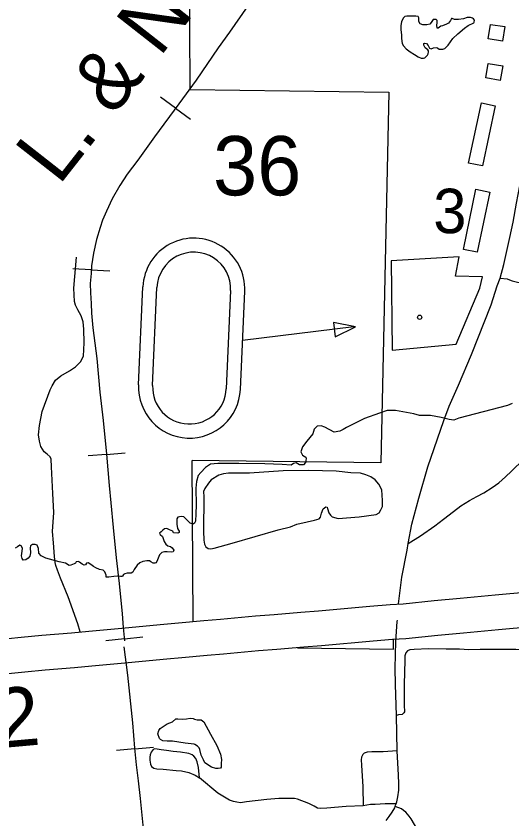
# Model space of a CAD drawing. Extents: x 61396 to 64680, y 55472 to 57605.
# Drawn here: x 62743.1 to 62853.4, y 56330.1 to 56508.8 of the extents above; entities that cross this region are included whole.
import ezdxf

# ---------------------------------------------------------------- set-up
doc = ezdxf.new("R2010")
doc.units = 0
for name, color, linetype in [('15', 7, 'Continuous'), ('33', 7, 'Continuous'), ('34', 7, 'Continuous'), ('35', 7, 'Continuous'), ('40', 7, 'Continuous'), ('48', 7, 'Continuous'), ('5', 7, 'Continuous'), ('56', 7, 'Continuous'), ('57', 7, 'Continuous'), ('6', 7, 'Continuous'), ('7', 7, 'Continuous')]:
    doc.layers.add(name, color=color, linetype=linetype)

msp = doc.modelspace()

# ---------------------------------------------------------------- linework, layer by layer
at = {"layer": '15'}
for points in [[(62738.41, 56369.93), (62744.28, 56370.54), (62748.87, 56370.99), (62755.43, 56371.52), (62759.28, 56371.87), (62766.65, 56372.54), (62768.95, 56372.72), (62775.96, 56373.42), (62779.27, 56373.69), (62784.86, 56374.24), (62788.56, 56374.57), (62796.35, 56375.24), (62800.5, 56375.57), (62806.45, 56376.07), (62810.4, 56376.39), (62821.81, 56377.41), (62826.31, 56377.8), (62829.16, 56377.92), (62836.11, 56378.7), (62841.9, 56379.23), (62849.65, 56379.94), (62857.08, 56380.61)], [(62857.78, 56372.83), (62850.36, 56372.16), (62842.61, 56371.45), (62836.9, 56370.93), (62829.76, 56370.12), (62826.8, 56370), (62822.49, 56369.63), (62811.07, 56368.6), (62807.09, 56368.28), (62801.13, 56367.78), (62797, 56367.46), (62789.24, 56366.78), (62785.59, 56366.46), (62779.97, 56365.91), (62776.66, 56365.64), (62769.63, 56364.94), (62767.3, 56364.76), (62759.99, 56364.09), (62756.09, 56363.73), (62749.56, 56363.21), (62745.06, 56362.77), (62739.07, 56362.15)]]:
    msp.add_lwpolyline(points, dxfattribs=at)
at = {"layer": '33'}
for points in [[(62850.75, 56450.39), (62851.59, 56453.46), (62852.21, 56456.17), (62852.92, 56459.47), (62853.63, 56462.9), (62854.39, 56467.13), (62855.91, 56474.83), (62857.24, 56482.13), (62859.07, 56492.04)], [(62830.28, 56391.36), (62831.1, 56395.71), (62832.7, 56401.45), (62834.69, 56408.43), (62838.22, 56418.71), (62839.46, 56421.96), (62841.47, 56426.58), (62844.4, 56433.45), (62848.8, 56444.5), (62850.11, 56448.74), (62850.75, 56450.39)], [(62828.14, 56377.95), (62828.92, 56383.9), (62830.05, 56389.91), (62830.28, 56391.36)], [(62825.39, 56329.74), (62826.08, 56330.63), (62826.78, 56331.58), (62827.34, 56332.58), (62827.44, 56332.88), (62827.52, 56333.12), (62827.62, 56333.41), (62827.78, 56333.88), (62828.01, 56334.99), (62828.21, 56336.47), (62828.25, 56337.94), (62828.17, 56339.83), (62827.88, 56345.25), (62827.69, 56353.12), (62827.52, 56359.99), (62827.44, 56363.6), (62827.57, 56369.6), (62827.88, 56374.02), (62827.9, 56374.3)], [(62862.33, 56367.78), (62857.94, 56367.71), (62854.27, 56367.82), (62851.05, 56367.78), (62846.35, 56367.78), (62843.81, 56367.71), (62841.69, 56367.85), (62838.74, 56367.85), (62834.86, 56367.92), (62831.64, 56367.82)], [(62831.64, 56367.82), (62830.78, 56367.71), (62830.71, 56367.69), (62830.13, 56367.47), (62829.79, 56367.03), (62829.58, 56366.34), (62829.58, 56365.35), (62829.41, 56360.04), (62829.41, 56355.15), (62829.51, 56354.17), (62829.48, 56353.9), (62829.35, 56353.69), (62829.15, 56353.47), (62828.95, 56353.35), (62828.17, 56353.21), (62827.69, 56353.12)], [(62844.89, 56306.79), (62844.25, 56308.66), (62840.74, 56313.99), (62834.09, 56324.8), (62832.69, 56327.19), (62830.99, 56330.09), (62830.52, 56330.69), (62829.79, 56331.6), (62829.27, 56331.98), (62828.82, 56332.33), (62827.44, 56332.88)]]:
    msp.add_lwpolyline(points, dxfattribs=at)
at = {"layer": '34'}
for points in [[(62757.35, 56371.69), (62756.88, 56373.47), (62754.67, 56379.5), (62753.01, 56383.69), (62752.34, 56385.41), (62751.93, 56386.5), (62751.79, 56387.11), (62751.63, 56388.48), (62751.45, 56391.52), (62751.22, 56394.07), (62751.5, 56398.3), (62751.31, 56402.48), (62751, 56408.44), (62750.95, 56410.13), (62750.68, 56410.67), (62750.04, 56411.26), (62749.4, 56411.76), (62748.99, 56412.4), (62748.63, 56412.99), (62748.31, 56414.17), (62748.13, 56415.58), (62748.36, 56417.63), (62748.95, 56420.78), (62750.7, 56425.57), (62751.13, 56426.48), (62751.91, 56427.7), (62753.08, 56428.7), (62755, 56429.78), (62756.33, 56430.7), (62757.46, 56431.82), (62758.09, 56433.08), (62758.25, 56436), (62758.2, 56439.1), (62758.03, 56440.72), (62757.59, 56442.01), (62756.82, 56443.39), (62756.36, 56444.4), (62756.14, 56445.2), (62755.95, 56448.22), (62756.55, 56455.09)], [(62850.75, 56450.39), (62852.3, 56450.28), (62852.84, 56450.08), (62853.46, 56449.8), (62854.61, 56449.5), (62856.32, 56449.38), (62858.37, 56449.32), (62860.28, 56449.19), (62861.23, 56449.22), (62861.77, 56449.34), (62862.4, 56449.46), (62863.1, 56449.58), (62864.1, 56449.7)], [(62830.28, 56391.36), (62833.02, 56393.05), (62836.2, 56395.27), (62838.18, 56396.79), (62841.32, 56399.23), (62842.02, 56399.78), (62843.97, 56400.92), (62845.56, 56401.81), (62847.13, 56402.65), (62849.01, 56403.81), (62850.48, 56404.89), (62851.93, 56406.2), (62853.3, 56407.5), (62855.98, 56410.05), (62857.84, 56411.74), (62861.24, 56414.64), (62863.38, 56416.55)], [(62783.92, 56339.24), (62783.7, 56341.52), (62783.38, 56342.81), (62783.07, 56343.51), (62782.65, 56344.06), (62782.27, 56344.34), (62781.5, 56344.66), (62779.65, 56344.93), (62778.05, 56345.11), (62776.55, 56345.28), (62775.4, 56345.49), (62774.5, 56345.63), (62773.99, 56345.64), (62773.63, 56345.56), (62773.14, 56344.97), (62772.9, 56344.34), (62772.83, 56343.82), (62772.86, 56343.12), (62773, 56342.25), (62773.25, 56341.73), (62773.73, 56341.38), (62774.43, 56341.21), (62775.86, 56341.17), (62778.71, 56340.86), (62779.93, 56340.76), (62781.54, 56340.44), (62782.96, 56339.81), (62783.92, 56339.24)], [(62827.88, 56345.25), (62824.77, 56345.04), (62823.84, 56345.03), (62822.22, 56345), (62821.18, 56344.97), (62820.55, 56344.73), (62820.2, 56344.45), (62819.92, 56343.82), (62819.89, 56343.23), (62819.92, 56342.01), (62820.2, 56337.24), (62820.32, 56332.97)], [(62820.32, 56332.97), (62816.51, 56332.81), (62812.23, 56332.47), (62810.73, 56332.4), (62810.14, 56332.47), (62809.4, 56332.92), (62808.22, 56333.48), (62805.71, 56334.45), (62805.01, 56334.66), (62804.42, 56334.63), (62803.8, 56334.63), (62801.57, 56334.59), (62798.85, 56334.38), (62794.39, 56333.89), (62793.03, 56333.69), (62792.2, 56333.79), (62791.43, 56333.93), (62790.59, 56334.24), (62787.98, 56335.81), (62783.92, 56339.24)], [(62827.62, 56333.41), (62825.22, 56333.41), (62822.96, 56333.31), (62821.91, 56333.27), (62820.32, 56332.97)]]:
    msp.add_lwpolyline(points, dxfattribs=at)
at = {"layer": '35'}
for points in [[(62829.28, 56502.12), (62829.86, 56501.45), (62830.76, 56500.77), (62831.75, 56500.19), (62832.56, 56499.7), (62833.19, 56499.38), (62833.68, 56499.38), (62834, 56499.47), (62834.58, 56500.05), (62834.76, 56500.37), (62834.85, 56500.77), (62834.85, 56501.04), (62834.67, 56501.27), (62834.4, 56501.45), (62834.09, 56501.67), (62833.77, 56502.26), (62833.82, 56502.62), (62834, 56502.71), (62834.36, 56502.66), (62834.76, 56502.17), (62835.08, 56501.58), (62835.39, 56501.49), (62835.93, 56501.67), (62836.65, 56501.76), (62836.88, 56501.63), (62837.19, 56501.4), (62837.46, 56501.4), (62838.04, 56501.4), (62838.49, 56501.54), (62839.21, 56502.3), (62840.25, 56503.78), (62841.32, 56504.82), (62842.85, 56506.03), (62843.66, 56506.62), (62844.88, 56507.24), (62845.01, 56507.42), (62845.06, 56507.83), (62844.83, 56508.1), (62844.61, 56508.28), (62844.16, 56508.46), (62843.39, 56508.41), (62842.63, 56508.1), (62841.5, 56507.96), (62840.61, 56508.01), (62840.11, 56508.23), (62839.93, 56508.23), (62839.71, 56507.78), (62839.3, 56507.15), (62838.85, 56506.93), (62837.95, 56506.57), (62837.55, 56506.48), (62836.97, 56506.08), (62836.74, 56506.08), (62836.7, 56506.71), (62836.74, 56507.24), (62836.74, 56507.74), (62836.52, 56508.01), (62835.89, 56508.01), (62835.71, 56507.78), (62835.44, 56507.29), (62835.12, 56506.93), (62834.45, 56506.79), (62833.59, 56506.79), (62833.01, 56507.02), (62832.65, 56507.51), (62832.65, 56507.87), (62832.65, 56508.37), (62832.52, 56508.68), (62831.98, 56508.73), (62830.9, 56508.73), (62830, 56508.73), (62829.55, 56508.68), (62829.19, 56508.32), (62828.79, 56507.47), (62828.7, 56506.66), (62828.7, 56505.67), (62828.83, 56504.59), (62828.83, 56503.87), (62828.87, 56503.19), (62828.97, 56502.66), (62829.28, 56502.12)], [(62853.42, 56422.5), (62852.41, 56422.09), (62841.54, 56419.25), (62840.48, 56418.82), (62839.43, 56418.96), (62837.61, 56419.43), (62835.26, 56419.88), (62832.86, 56419.85), (62831.54, 56420.25), (62827.5, 56420.99), (62825.67, 56421), (62823.93, 56420.39), (62820.62, 56419.18), (62816.57, 56417.17), (62815.88, 56416.73), (62815.08, 56416.37), (62813.86, 56416.15), (62811.75, 56417.24)], [(62811.75, 56417.24), (62810.97, 56417.56), (62810.05, 56417.51), (62809.42, 56416.79), (62809.09, 56415.78), (62807.75, 56414.16), (62806.83, 56412.88), (62806.41, 56411.78), (62806.8, 56411.06), (62807.54, 56410.59), (62807.66, 56410.26), (62807.48, 56409.39), (62807, 56408.88), (62806.14, 56408.88), (62805.42, 56409.3), (62804.79, 56409.18), (62804.27, 56408.84), (62802.3, 56408.95), (62798.43, 56409.07), (62792.68, 56409.15), (62788.01, 56409.15), (62786.32, 56409.01), (62785.26, 56408.32), (62784.23, 56407.21), (62783.6, 56406.49), (62783.23, 56405.2)], [(62783.23, 56405.2), (62783.11, 56403.72), (62783.18, 56399.99), (62783.12, 56397.98), (62782.98, 56396.33), (62782.78, 56395.87), (62782.47, 56395.69), (62781.82, 56395.89), (62781.29, 56396.42), (62780.44, 56397.34), (62779.86, 56397.38), (62779.08, 56397.2)], [(62779.08, 56397.2), (62778.88, 56396.87), (62778.86, 56395.64), (62779.02, 56394.71), (62779.26, 56394.37), (62779.41, 56394.11), (62779.35, 56393.83), (62779.08, 56393.66), (62778.15, 56393.77), (62777.97, 56394.15), (62777.22, 56394.41), (62776.61, 56394.69), (62776.1, 56394.67), (62775.72, 56394.34), (62775.38, 56393.96), (62775.01, 56393.67), (62775.16, 56393.41), (62775.69, 56392.91), (62776.07, 56391.85), (62776.44, 56391.22), (62776.89, 56390.87), (62777.49, 56390.67), (62777.81, 56390.4), (62778.18, 56389.9), (62778.16, 56389.68), (62778.03, 56389.49), (62777.68, 56389.48), (62777.68, 56389.48)], [(62760.31, 56386.27), (62759.76, 56386.73), (62759.16, 56387.06), (62758.75, 56386.96), (62758.52, 56386.64), (62758.27, 56386.55), (62757.83, 56386.8), (62757.2, 56387.25), (62756.94, 56387.35), (62756.5, 56387.33), (62756.36, 56386.99), (62756, 56386.83), (62755.28, 56386.53), (62754.89, 56386.5), (62754.09, 56387.01), (62752.67, 56387.26), (62749.71, 56388.13), (62748.7, 56388.66), (62748.19, 56389.21), (62748.08, 56390.27), (62747.78, 56391), (62747.34, 56391.14), (62746.75, 56391.14), (62746.36, 56390.82), (62746.22, 56390.43), (62746.29, 56389.33)], [(62746.29, 56389.33), (62746.16, 56388.57), (62745.82, 56388.13), (62745.28, 56387.74), (62744.73, 56387.69), (62744.47, 56388.02), (62744.31, 56388.62), (62744.5, 56389.69), (62744.52, 56390.31), (62744.26, 56390.89), (62743.92, 56391.03), (62743.43, 56390.66), (62742.92, 56390.33)], [(62777.68, 56389.48), (62776.71, 56389.51), (62776.12, 56389.54), (62775.56, 56389.35), (62775.03, 56388.85), (62774.7, 56388.14), (62774.42, 56387.38), (62774.22, 56387.1), (62773.97, 56386.99), (62773.59, 56387), (62773.11, 56387.3), (62772.78, 56387.51), (62772.16, 56387.55), (62771.33, 56387.37), (62770.64, 56387.05), (62770.07, 56386.55), (62769.38, 56385.59), (62769.06, 56385.03), (62768.7, 56384.79), (62767.82, 56384.79), (62767.27, 56384.65), (62767.02, 56384.47), (62766.8, 56384.11), (62766.62, 56384.02), (62766.36, 56384), (62765.67, 56384.13), (62764.85, 56384.04), (62763.78, 56383.87), (62763.18, 56383.87), (62763.14, 56384.32), (62762.84, 56385.06), (62762.49, 56385.47), (62761.64, 56385.56), (62760.84, 56385.98), (62760.31, 56386.27)], [(62782.72, 56346.75), (62780.71, 56346.96), (62777.88, 56347.37), (62776.74, 56347.37), (62775.76, 56347.47), (62775.25, 56347.73), (62775.04, 56347.99), (62774.63, 56349.02), (62774.84, 56349.79), (62775.15, 56350.21), (62776.74, 56351.24), (62777.88, 56351.7), (62778.65, 56352.32), (62779.12, 56352.32), (62780.2, 56352.27), (62781.02, 56352.32), (62781.8, 56352.47), (62782.47, 56352.42), (62782.83, 56352.27), (62783.39, 56352.11), (62783.96, 56352.11), (62784.27, 56352.11), (62784.84, 56351.65), (62786.33, 56348.97), (62787.73, 56346.39), (62788.55, 56344.48), (62788.81, 56343.3), (62788.76, 56342.42), (62788.76, 56341.6), (62788.6, 56341.39), (62788.09, 56341.29), (62787.52, 56341.29), (62786.54, 56341.6), (62785.1, 56342.58), (62784.79, 56343.25), (62784.27, 56344.28), (62783.96, 56345.52), (62783.81, 56345.88), (62783.45, 56346.29), (62782.88, 56346.65), (62782.72, 56346.75)]]:
    msp.add_lwpolyline(points, dxfattribs=at)
msp.add_lwpolyline([(62788.2, 56406.6), (62786.51, 56405.53), (62785.88, 56404.77), (62785.08, 56403.65), (62784.81, 56402.94), (62784.85, 56401.74), (62784.81, 56394.11), (62784.85, 56392.14), (62785.03, 56391.21), (62785.34, 56390.63), (62785.84, 56390.27), (62786.46, 56390.18), (62787.17, 56390.36), (62791.15, 56391.43), (62801.37, 56394.42), (62804.14, 56395.09), (62805.52, 56395.67), (62807.88, 56396.16), (62809.49, 56396.56), (62810.52, 56396.83), (62810.83, 56397.27), (62811.01, 56398.12), (62811.41, 56399.06), (62812.03, 56399.5), (62812.26, 56399.46), (62812.39, 56399.19), (62812.7, 56398.21), (62813.02, 56397.68), (62813.37, 56397.32), (62814.76, 56396.92), (62819.44, 56397.32), (62823.19, 56397.81), (62823.86, 56398.21), (62824.26, 56398.84), (62824.62, 56399.59), (62824.62, 56400.93), (62824.44, 56403.34), (62823.82, 56404.55), (62822.97, 56405.53), (62822.03, 56406.2), (62820.92, 56406.64), (62819.67, 56407.05), (62817.57, 56407.13), (62814.31, 56407.49), (62808.24, 56407.63), (62802.48, 56407.54), (62795.03, 56407.05), (62790.34, 56407), (62789.27, 56406.87)], close=True, dxfattribs=at)
at = {"layer": '40'}
for p, q in [((62778.59, 56488.26), (62775.27, 56490.71)), ((62778.59, 56488.26), (62781.92, 56485.82)), ((62759.84, 56452.26), (62755.72, 56452.48)), ((62759.84, 56452.26), (62763.96, 56452.03)), ((62763.24, 56411.21), (62759.13, 56410.85)), ((62763.24, 56411.21), (62767.35, 56411.57)), ((62767.2, 56370.15), (62763.1, 56369.68)), ((62767.2, 56370.15), (62771.3, 56370.61)), ((62769.56, 56345.69), (62765.45, 56345.33)), ((62769.56, 56345.69), (62773.67, 56346.05))]:
    msp.add_line(p, q, dxfattribs=at)
for points in [[(62794.66, 56511.05), (62790.55, 56505.18), (62788.08, 56501.71), (62783.15, 56494.46), (62779.28, 56489.2), (62773.89, 56481.86), (62770.21, 56476.69), (62767.83, 56473.58), (62766.16, 56471.06), (62764.45, 56468.07), (62763.21, 56465.3), (62762.32, 56463.35), (62761.8, 56461.68), (62761.01, 56459), (62760.31, 56456.02), (62759.89, 56453.16), (62759.8, 56451.48), (62759.61, 56449.26), (62759.67, 56447.19), (62759.8, 56444.79), (62759.89, 56442.63), (62760.22, 56439.4), (62761.1, 56432.55), (62761.74, 56425.03), (62762.47, 56418.73), (62763.24, 56411.25), (62763.84, 56404.31), (62764.21, 56400.41), (62764.73, 56394.9), (62765.37, 56388.17), (62766.01, 56382.48), (62766.68, 56375.72), (62766.92, 56372.65), (62767.25, 56369.7)], [(62794.66, 56511.05), (62790.55, 56505.18), (62788.08, 56501.71), (62783.15, 56494.46), (62779.28, 56489.2), (62773.89, 56481.86), (62770.21, 56476.69), (62767.83, 56473.58), (62766.16, 56471.06), (62764.45, 56468.07), (62763.21, 56465.3), (62762.32, 56463.35), (62761.8, 56461.68), (62761.01, 56459), (62760.31, 56456.02), (62759.89, 56453.16), (62759.8, 56451.48), (62759.61, 56449.26), (62759.67, 56447.19), (62759.8, 56444.79), (62759.89, 56442.63), (62760.22, 56439.4), (62761.1, 56432.55), (62761.74, 56425.03), (62762.47, 56418.73), (62763.24, 56411.25), (62763.84, 56404.31), (62764.21, 56400.41), (62764.73, 56394.9), (62765.37, 56388.17), (62766.01, 56382.48), (62766.68, 56375.72), (62766.92, 56372.65), (62767.25, 56369.7)], [(62776.55, 56277.19), (62776.5, 56279.36), (62776.12, 56281.92), (62775.92, 56284.47), (62775.14, 56291.4), (62774.79, 56295.84), (62774.17, 56301.39), (62773.61, 56306.69), (62772.72, 56314.93), (62771.95, 56323.03), (62771.37, 56328.69), (62770.81, 56334.62), (62770.37, 56338.57), (62769.88, 56342.08), (62769.55, 56345.85), (62769.06, 56351.43), (62767.95, 56362.08), (62767.19, 56368.41)], [(62771.37, 56328.69), (62770.81, 56334.62), (62770.37, 56338.57), (62769.88, 56342.08), (62769.55, 56345.85), (62769.06, 56351.43), (62767.95, 56362.08), (62767.19, 56368.41)]]:
    msp.add_lwpolyline(points, dxfattribs=at)
at = {"layer": '56'}
for points in [[(62848.1, 56503.67), (62848.58, 56506.88), (62851.81, 56506.4), (62851.32, 56503.18)], [(62847.56, 56494.99), (62848.11, 56498.19), (62851.33, 56497.65), (62850.78, 56494.44)], [(62846.6, 56489.43), (62849.66, 56488.77), (62846.81, 56475.4), (62843.75, 56476.05)], [(62845.38, 56470.22), (62848.44, 56469.58), (62845.65, 56456.19), (62842.59, 56456.83)]]:
    msp.add_lwpolyline(points, close=True, dxfattribs=at)
at = {"layer": '57'}
for p, q in [((62770.37, 56426.65), (62771.32, 56448.51)), ((62773.49, 56426.52), (62774.45, 56448.37)), ((62789.88, 56425.8), (62790.84, 56447.65)), ((62793, 56425.66), (62793.96, 56447.51))]:
    msp.add_line(p, q, dxfattribs=at)
msp.add_lwpolyline([(62793.48, 56436.59), (62818.19, 56439.63)], dxfattribs=at)
msp.add_lwpolyline([(62813.69, 56440.55), (62814.08, 56437.39), (62818.63, 56439.56)], close=True, dxfattribs=at)
msp.add_circle((62832.86, 56441.72), 0.469, dxfattribs=at)
for centre, radius, start, end in [((62782.64, 56448.01), 11.33, 357.488, 177.488), ((62782.64, 56448.01), 8.2, 357.488, 177.488), ((62781.68, 56426.16), 11.33, 177.488, 357.488), ((62781.68, 56426.16), 8.2, 177.488, 357.488)]:
    msp.add_arc(centre, radius, start, end, dxfattribs=at)
at = {"layer": '6'}
for points in [[(62781.84, 56492.38), (62781.6, 56534.3)], [(62781.84, 56492.38), (62826.04, 56491.8), (62824.24, 56409.32), (62782.31, 56409.87)], [(62782.51, 56374.01), (62782.31, 56409.87)], [(62805.68, 56368.16), (62827.02, 56367.89), (62827.05, 56369.99)]]:
    msp.add_lwpolyline(points, dxfattribs=at)
at = {"layer": '7'}
msp.add_lwpolyline([(62841.66, 56455.18), (62826.53, 56454.28), (62826.75, 56434.38), (62840.95, 56435.7), (62846.24, 56448.16), (62846.83, 56450.69), (62840.82, 56450.85), (62841.66, 56455.18)], dxfattribs=at)

# ---------------------------------------------------------------- texts
at = {"layer": '40'}
msp.add_text('L. & N. W.', height=13.2, rotation=51.8882, dxfattribs=at).set_placement((62752.62, 56470.84))
at = {"layer": '48'}
msp.add_text('2.2', height=13.2, rotation=5.1513, dxfattribs=at).set_placement((62724.37, 56344.45))
at = {"layer": '5'}
msp.add_text('36', height=13.2, dxfattribs=at).set_placement((62786.91, 56468.85))
at = {"layer": '56'}
msp.add_text('3', height=9.9, dxfattribs=at).set_placement((62835.89, 56460.43))

doc.saveas('drawing.dxf')
